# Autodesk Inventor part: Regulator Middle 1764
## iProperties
Created: 2010-02
Part Number: Regulator Middle 1764
Document SubType Name: Modeling
Designer: jgehrig
Density: 1 g/cm^3
Author: jgehrig
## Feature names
1. Extrusion1
2. Extrusion2
3. Extrusion3
4. Extrusion4
5. Extrusion5
6. Extrusion6
7. Circular Pattern1
8. Fillet1
